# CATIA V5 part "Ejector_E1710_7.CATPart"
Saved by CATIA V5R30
Part number: Vyhazovac_2.5x160_5
Nomenclature: E1710/2.5x160
Description: MEUSBURGER
Property "Material": "1.221"
Publications: "__DrillHole", "Base"
Bounding box of the stored display mesh (mm): x -2.499 to 2.499, y -2.499 to 2.499, z 0 to 152
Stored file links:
  E:\Bakalarka\Model\Forma_v7\Ejector_E1710_7.CATPart
  E:\dev\MoldDesign\intel_a\startup\components\MoldCatalog\Ejector\Meusburger\Ejector_E1710\TableE1710.txt
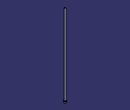
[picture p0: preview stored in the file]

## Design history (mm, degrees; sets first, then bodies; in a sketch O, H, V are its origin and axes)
Parameters
  Ref = "E1710/2.5x160" {design table}
  D1 = 2.5 mm {design table}
  D3 = 5 mm {design table}
  L = 160 mm {design table}
  L3 = 2 mm {design table}
  R = 0.3 mm {design table}
  k_d3 = 6 mm {design table}
  k_d1 = 2.7 mm {design table}
  k_F = 0.3 mm {design table}
  kl = 17 mm {design table}
  Mat = "1.221" {design table}
  HeatTreat = "ISO6751" {design table}
  Offset_Parting = 10 mm
  Anti_Rotation = "Normal"
  Anti_Rotation_D = 1.55 mm
  Anti_Rotation_D_Icut = 1.55 mm
  Add_Length_L = 0.0877 mm
  Add_Length_D3 = 0 mm
  SupplierRef = "Meusburger 2017"
  BmpRef = "F_MldEjectorD1"
  DrillHole_Length = 225 mm
  ValidationTest = false
  Anti_Rotation_D_min = 1.55 mm {= OffSet_D1 /2}
  Anti_Rotation_D_max = 2.425 mm {= D3/2-0.075mm}
  Anti_Rotation_D_ref = 1.55 mm {= Anti_Rotation_D}
  Anti_Rotation_D_Icut_ref = 1.55 mm {= Anti_Rotation_D_Icut}
  Anti_Rotation_Ref_Icut = 2.3246 mm
  Offset_L = 20 mm
  D = 2.5 mm {= D1}
  OffSet_D1 = 3.1 mm {= D1+2*R}
  OffSet_D3 = 6 mm {= D3+1mm}
  XG_Split = 44.5 mm
  YG_Split = 54.5 mm
  ZG_Split = -198 mm
  DirX_Split = 0 mm
  DirY_Split = 0 mm
  DirZ_Split = 1 mm
Set1 "BaseBody"
  Point1 "Base": (0, 0, 0)
  Plane1: type Offset, RefPlane xy-plane, Offset 225 {= DrillHole_Length}, reversed
  Sketch1 "Sketch.2" on xy-plane, origin (0, 0, 0), H (1, 0, 0), V (0, 1, 0)
    point P1 (-0.46, 1.1623)
    point P2 (0.46, 1.1623)
    construction line L1 (-0.46, 1.1623) -> (0.46, 1.1623)
    point P3 (0.46, -1.1623)
    line L2 (0.46, -1.1623) -> (0.46, 1.1623)
    point P4 (-0.46, -1.1623)
    construction line L3 (0.46, -1.1623) -> (-0.46, -1.1623)
    line L4 (-0.46, 1.1623) -> (-0.46, -1.1623)
    point P5 (-0.21, 1.1623)
    arc A1 centre (-0.21, 1.1623) radius 0.25 from (-0.21, 1.4123) to (-0.46, 1.1623) ccw
    point P7 (0.21, 1.1623)
    point P8 (0.21, 1.4123)
    arc A2 centre (0.21, 1.1623) radius 0.25 from (0.46, 1.1623) to (0.21, 1.4123) ccw
    line L5 (-0.21, 1.4123) -> (0.21, 1.4123)
    point P9 (-0.46, -1.1623)
    arc A3 centre (-0.21, -1.1623) radius 0.25 from (-0.46, -1.1623) to (-0.21, -1.4123) ccw
    point P11 (0.21, -1.4123)
    line L6 (-0.21, -1.4123) -> (0.21, -1.4123)
    point P12 (0.46, -1.1623)
    arc A4 centre (0.21, -1.1623) radius 0.25 from (0.21, -1.4123) to (0.46, -1.1623) ccw
    point P14 (-0.46, 1.1623)
    point P15 (-0.46, -1.1623)
    point P16 (0.46, 1.1623)
    point P17 (0.46, -1.1623)
    reference projected circle E1 centre (0, 0) radius 1.25 from edge [face of Shaft1 from Sketch2.L3 | face of Shaft1 from Sketch2.L4]
    reference projected circle E2 centre (0, 0) radius 1.25 from edge [face of Shaft1 from Sketch2.L3 | face of Shaft1 from Sketch2.L4]
    reference projected circle E3 centre (0, 0) radius 1.25 from edge [face of Shaft1 from Sketch2.L3 | face of Shaft1 from Sketch2.L4]
    reference projected circle E4 centre (0, 0) radius 1.25 from edge [face of Shaft1 from Sketch2.L3 | face of Shaft1 from Sketch2.L4]
    point P18 (-0.46, -1.1623)
    point P19 (-0.21, -1.4123)
    point P20 (0.21, -1.4123)
    point P21 (0.46, -1.1623)
    point P22 (-0.21, -1.4123)
    point P23 (0.21, -1.4123)
    distance P14 P15 = 2.3246 (reference)
    distance P16 P17 = 2.3246 (reference)
    distance L1 P14 = 0 (reference)
    radius A1 = 1.25
    distance L4 V = 1.56
    distance L2 V = 2.435
    distance L5 L6 = 5
    horizontal: L1 H, L3 H, L5 H
    vertical: L2 V, L4 V
    coincidence: P5 L1, P7 L1, P3 P12, P14 L4, P15 L4, P16 L2, P17 L2, P14 E1, P15 E2, P16 E3, P17 E4, P3 P21, P4 P18, P20 P23, P19 P22
    tangency: A1 L4, A2 L2, A2 L5, A1 L5
    symmetry: P1 P9 H, A1 A3 H, P8 P11 H, L5 L6 H, P2 P12 H, A2 A4 H
  DatumSurface1
Body1 "PartBody" (main body)
  Sketch2 "Sketch.1" on zx-plane, origin (0, 0, 0), H (-1, 0, 0), V (0, 0, 1)
    point P1 (0, 160)
    line L1 (1.25, 160) -> (0, 160)
    line L2 (1.25, 2) -> (1.25, 160)
    line L3 (2.5, 2) -> (1.25, 2)
    line L4 (2.5, 0) -> (2.5, 2)
    point P5 (0, 0)
    line L5 (0, 0) -> (2.5, 0)
    point P6 (0, 160)
    axis line L6 (0, 160) -> (0, 0)
    point P7 (0, 0)
    point P8 (1.25, 2)
    point P9 (1.25, 2)
    line L7 (0, 160) -> (0, 0)
    distance L5 L3 = 2 {= L3}
    distance L5 L1 = 160 {= L}
    distance L2 L6 = 1.25 {= D1 /2}
    distance L4 L6 = 2.5 {= D3 /2}
    coincidence: L6 P5, P1 L6, L5 H, L6 V, P7 O, P6 P1, P8 P9
    vertical: L2 V, L7 V
    horizontal: L1 H
  Shaft1 "Shaft.1": profile Sketch2, axis Sketch2.L6, angle 360
  Pocket1 "Pocket.1": profile Sketch1, direction (0, 0, 1), length 3, outer side, deactivated
  Pocket2 "Pocket.2": profile Sketch1, direction (0, 0, 1), length 3, outer side, deactivated
  Fillet1: radius 0.3 {= R}, on edge [face of Shaft1 from Sketch2.L2 | face of Shaft1 from Sketch2.L3]
  Pocket3: profile face of Shaft1 from Sketch2.L1, direction along face of Shaft1 from Sketch2.L1 reversed, up to face of DatumSurface1
Body2 "__DrillHole"
  Sketch3 "Sketch.3" on face of Shaft1, origin (0, 0, 0), H (1, 0, 0), V (0, -1, 0)
    point P1 (0, 0)
    reference projected point E1 (0, 0) from Point1
    coincidence: E1 P1
  Hole1 "Hole.1": placed by Sketch3, at (0, 0, 0) direction (0, 0, 1), diameter 3.1 {= OffSet_D1}, depth 140 {= L-Offset_L}
  Sketch4 "Sketch.4" on face of Shaft1, origin (0, 0, 0), H (1, 0, 0), V (0, -1, 0)
    point P1 (0, 0)
    reference projected point E1 (0, 0) from Point1
    coincidence: E1 P1
  Hole2 "Hole.2": placed by Sketch4, at (0, 0, 0) direction (0, 0, 1), diameter 2.5 {= D1}, depth 160 {= L}
  Sketch5 "Sketch.5" on face of Shaft1 from Sketch2.L3, origin (0, 0, 2), H (1, 0, 0), V (0, 1, 0)
    point P1 (0, 0)
    reference projected point E1 (0, 0) from Point1
    coincidence: E1 P1
  Hole3 "Hole.3": placed by Sketch5, at (0, 0, 2) direction (0, 0, -1), diameter 6 {= OffSet_D3}, depth 227 {= L3 +DrillHole_Length}
  Chamfer1: length 0.3 {= k_F}, angle 45, on edge [face of Hole1 | face of Hole3]
  Body3 "__Body.1"
    Pocket4 "Pocket.3": profile Sketch1, direction (0, 0, -1), length 225, opposite side length 2, deactivated
  Assemble1: tool Body3
  Chamfer2: length 0.3 {= k_F}, angle 45, on edge [start face of Pocket4 | face of Hole1], deactivated
  Body4 "__Body.2"
    Pocket5 "Pocket.4": profile Sketch1, direction (0, 0, -1), length 225, opposite side length 2, deactivated
  Assemble2: tool Body4
  Chamfer3: length 0.3 {= k_F}, angle 45, on edge [start face of Pocket5 | face of Hole1], deactivated
Relations
  design table "TableE1710", configuration 134, drives Ref, D1, D3, L, L3, R, k_d3, k_d1, k_F, kl, Mat, HeatTreat
  Offset_L = 20mm (deactivated)
  rule "Cut_Head_rule":
    let sketch_cut (length)
    let PartBody_Pocket_Sketch (Boolean)
    let I_PartBody_Pocket (Boolean)
    let D_PartBody_Pocket (Boolean)
    let N_DrillHole_Hole (Boolean)
    let N_DrillHole_Hole_Sketch (Boolean)
    let I_DrillHole_Pocket (Boolean)
    let D_DrillHole_Pocket (Boolean)
    /* --------------------------------------------------------------------------------------*/
    if Anti_Rotation =="Normal"
    {
    	sketch_cut=Anti_Rotation_D_max
    	PartBody_Pocket_Sketch = false
    	I_PartBody_Pocket = false
    	D_PartBody_Pocket = false
    	N_DrillHole_Hole = true
    	N_DrillHole_Hole_Sketch = true
    	I_DrillHole_Pocket = false
    	D_DrillHole_Pocket = false
    	Chamfer1.Activity= true
    	Chamfer2.Activity= false
    	Chamfer3.Activity= false
    }
    if Anti_Rotation == "I_Cut"
    {
    	sketch_cut=Anti_Rotation_D_Icut_ref
    	PartBody_Pocket_Sketch = true
    	I_PartBody_Pocket = true
    	D_PartBody_Pocket = false
    	N_DrillHole_Hole = false
    	N_DrillHole_Hole_Sketch = false
    	I_DrillHole_Pocket = true
    	D_DrillHole_Pocket = false
    	Chamfer1.Activity= false
    	Chamfer2.Activity= true
    	Chamfer3.Activity= false
    }
    if Anti_Rotation =="D_Cut"
    {
    	sketch_cut=Anti_Rotation_D_max
    	PartBody_Pocket_Sketch = true
    	I_PartBody_Pocket = false
    	D_PartBody_Pocket = true
    	N_DrillHole_Hole = false
    	N_DrillHole_Hole_Sketch = false
    	I_DrillHole_Pocket = false
    	D_DrillHole_Pocket = true
    	Chamfer1.Activity= false
    	Chamfer2.Activity= false
    	Chamfer3.Activity= true
    }
    /* --------------------------------------------------------------------------------------*/
    Sketch1.distance(L2 V) = sketch_cut+0.01mm
    Sketch1.distance(L4 V) =Anti_Rotation_D_ref+0.01mm
    Sketch1.radius(A1) =D/2
    Pocket4.FirstLimit.Depth = DrillHole_Length
    Pocket5.FirstLimit.Depth = DrillHole_Length
    Pocket1.FirstLimit.Depth = L3+1mm
    Pocket2.FirstLimit.Depth = L3+1mm
    Pocket4.SecondLimit.Depth = L3
    Pocket5.SecondLimit.Depth =L3
    Pocket1.Activity = I_PartBody_Pocket
    Pocket2.Activity = D_PartBody_Pocket
    Sketch1.Activity =PartBody_Pocket_Sketch
    Hole3.Activity= N_DrillHole_Hole
    Sketch5.Activity = N_DrillHole_Hole_Sketch
    Pocket4.Activity = I_DrillHole_Pocket
    Pocket5.Activity  = D_DrillHole_Pocket
  rule "Anti_Rotation_Icut_constrain":
    let Ref1(length)
    let Ref2(length)
    let Ref3(length)
    let Diam1(length)
    let Diam2(length)
    let Add_Length_Lmin (length)
    Ref1=Sketch1.distance(P14 P15)
    Ref2=Sketch1.distance(P16 P17)
    Diam1=D
    Diam2=D3
    /* --------------------------------------------------------------------*/
    if Ref1 >Ref2
    	Anti_Rotation_Ref_Icut = Ref1
    else
    	Anti_Rotation_Ref_Icut  =Ref2
    Add_Length_D3 .InferiorRange=Anti_Rotation_Ref_Icut /2+Diam1/2 -Diam2/2
    if Add_Length_D3 .InferiorRange<0mm
    	Add_Length_D3 .InferiorRange=0mm
    if ValidationTest == "true"
    	Ref3   = 2*Add_Length_L +Anti_Rotation_Ref_Icut  +2*Diam1/2
    else
    	Ref3  =Diam2+2*Add_Length_D3
    if Ref3 <Diam2
    {
    	Ref3 =Diam2
    }
    /* --------------------------------------------------------------------*/
    Sketch1.distance(L5 L6) = Ref3
    Add_Length_L .InferiorRange=Diam2/2-Anti_Rotation_Ref_Icut/2-Diam1/2
    Add_Length_Lmin=Diam2/2-Anti_Rotation_Ref_Icut/2-Diam1/2
    if Add_Length_Lmin<0mm
    	Add_Length_L .InferiorRange=0mm
    else
    	Add_Length_L .InferiorRange=Add_Length_Lmin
